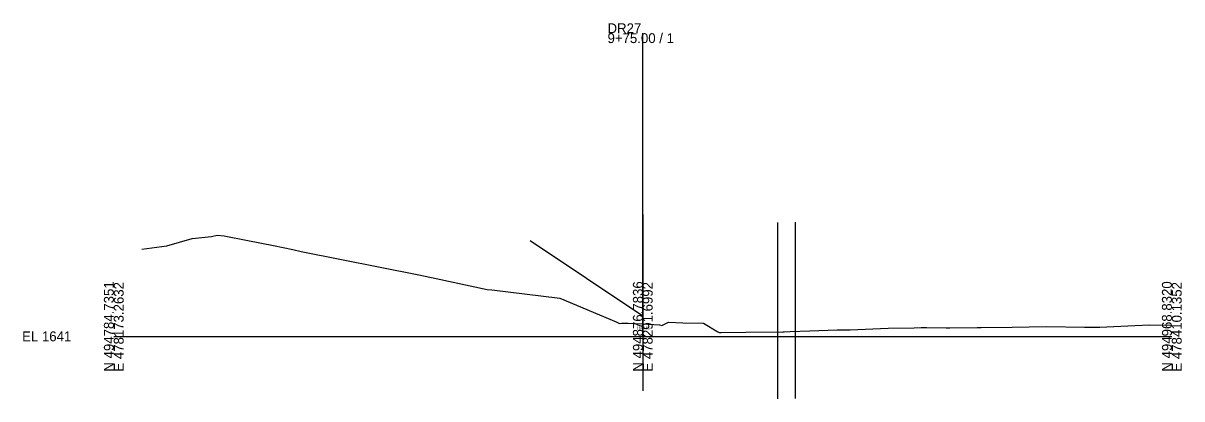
# Model space of a CAD drawing. Extents: x -26 to 478410, y -18 to 495058.
# Drawn here: x 1274.3 to 1602.8, y -17.7 to 88.8 of the extents above; entities that cross this region are included whole.
import ezdxf

# ---------------------------------------------------------------- set-up
doc = ezdxf.new("R2010")
doc.units = 0
for name, color, linetype in [('Exist Cross Section Cell', 7, 'Continuous'), ('Exist XS Center Line Elevation Label', 7, 'Continuous'), ('Exist XS Ground Line', 7, 'Continuous'), ('Scratch_Level_4', 7, 'Continuous'), ('Scratch_Level_5', 7, 'Continuous')]:
    doc.layers.add(name, color=color, linetype=linetype)

msp = doc.modelspace()

# ---------------------------------------------------------------- linework, layer by layer
at = {"layer": 'Exist Cross Section Cell'}
for p, q in [((1450, 0), (1450, 85.93)), ((1300, 0), (1450, 0)), ((1450, 0), (1600, 0))]:
    msp.add_line(p, q, dxfattribs=at)
at = {"layer": 'Exist XS Ground Line'}
msp.add_lwpolyline([(1307.94, 24.74), (1315.08, 25.65), (1322.19, 27.76), (1327.75, 28.32), (1329.32, 28.64), (1331.34, 28.45), (1338.02, 27.19), (1345.25, 25.71), (1350.8, 24.58), (1353.16, 24.08), (1386.53, 17.45), (1391.41, 16.37), (1405.89, 13.32), (1407.24, 13.16), (1426.47, 10.79), (1442.41, 4.09), (1442.81, 3.96), (1443.42, 3.69), (1444.09, 3.72), (1445.81, 3.75), (1447.52, 3.68), (1450, 3.55), (1454.72, 3.31), (1455.42, 3.12), (1457.28, 4.04), (1461.33, 3.88), (1467.2, 3.74), (1471.28, 1.26), (1471.66, 1.12), (1472.18, 1.11), (1479.17, 1.19), (1489.74, 1.31), (1490.13, 1.28), (1491.83, 1.33), (1497.4, 1.54), (1505.09, 1.84), (1508.78, 1.89), (1519.62, 2.28), (1526.93, 2.46), (1528.9, 2.47), (1530.43, 2.48), (1536.03, 2.42), (1537.05, 2.44), (1544.81, 2.5), (1545.92, 2.51), (1554.75, 2.64), (1559.53, 2.72), (1564.54, 2.79), (1575.26, 2.65), (1579.55, 2.58), (1589.55, 3.06), (1593.77, 3.26), (1600, 3.17)], dxfattribs=at)
at = {"layer": 'Scratch_Level_4'}
for p, q in [((1450, 34.55), (1450, -15.45)), ((1488.19, 32.29), (1488.19, -17.71)), ((1493.24, 32.39), (1493.24, -17.61))]:
    msp.add_line(p, q, dxfattribs=at)
at = {"layer": 'Scratch_Level_5'}
msp.add_line((1450, 5.72), (1418.02, 27.04), dxfattribs=at)

# ---------------------------------------------------------------- texts
at = {"layer": 'Exist Cross Section Cell'}
for s, p in [('DR27', (1440, 85.93)), ('9+75.00 / 1', (1440, 83.13)), ('EL 1641', (1274, -1.4))]:
    msp.add_text(s, height=2.8, dxfattribs=at).set_placement(p)
for s, p in [('N 494784.7351', (1300, -10)), ('E 478173.2632', (1302.8, -10)), ('N 494876.7836', (1450, -10)), ('E 478291.6992', (1452.8, -10)), ('N 494968.8320', (1600, -10)), ('E 478410.1352', (1602.8, -10))]:
    msp.add_text(s, height=2.8, rotation=90, dxfattribs=at).set_placement(p)
at = {"layer": 'Exist XS Center Line Elevation Label'}
msp.add_text('1644.55', height=0.75, dxfattribs=at).set_placement((1448.25, 2.01))

doc.saveas('drawing.dxf')
